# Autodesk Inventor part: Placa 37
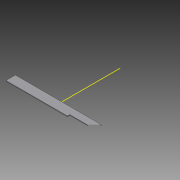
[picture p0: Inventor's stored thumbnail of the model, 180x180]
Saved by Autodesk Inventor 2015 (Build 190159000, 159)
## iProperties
Created: 2015-04
Part Number: Placa 37
Material: Generic
Document SubType Name: Modeling
Designer: suporte
Density: 1 g/cm^3
Appearance: Default
Author: suporte
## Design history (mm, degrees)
workplane "Work Plane1"
sketch "Sketch1"
  geometry: L1 (-669.015, -436.277)-(-663.251, -436.277) reference; L2 (-819.015, 332.281)-(-819.015, -586.277) reference; L3 (80.985, -586.277)-(-819.015, -586.277) reference; L4 (-819.015, -436.277)-(780.985, -436.277); L5 (780.985, -1073.777)-(780.985, -273.777) reference; L6 (80.985, -586.277)-(165.985, -586.277); L7 (780.985, -548.777)-(780.985, -436.277); L8 (165.985, 601.223)-(165.985, -673.777) reference; L9 (880.985, -548.777)-(-819.015, -548.777) reference; L10 (165.985, -586.277)-(165.985, -548.777); L11 (780.985, -548.777)-(165.985, -548.777); L12 (80.985, -586.277)-(-819.015, -586.277); L13 (-819.015, -436.277)-(-819.015, -586.277); 3 further points
  constraints: 14 end point, 8 point on line, 4 collinear, 1 horizontal, 1 midpoint, 1 perpendicular
extrude "Extrusion1" new body sketch "Sketch1" distance "d0" = 12.5; taper "d1" = 0 deg
body "Solid1"
node "Reference1"
node "Reference2"
node "Reference3"
node "Reference4"
node "Reference5"
node "Reference6"
